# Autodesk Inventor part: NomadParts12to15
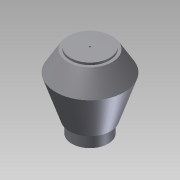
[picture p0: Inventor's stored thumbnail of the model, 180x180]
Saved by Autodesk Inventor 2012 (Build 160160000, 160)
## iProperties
Created: 2012-10
Part Number: NomadParts12to15
Material: Default
Document SubType Name: Modeling
Designer: TechShop Member
Density: 1 g/cm^3
Author: TechShop Member
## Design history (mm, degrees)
sketch "Sketch1"
  geometry: L1 (0, 0)-(57.15, 0); L2 (57.15, 0)-(57.15, 38.1); L3 (57.15, 38.1)-(65.088, 38.1); L4 (107.95, 166.319)-(65.088, 38.1); L5 (0, 236.53)-(61.722, 236.53); L6 (61.722, 236.53)-(61.722, 229.819); L7 (61.722, 229.819)-(70.3, 229.819); L8 (70.3, 229.819)-(107.95, 166.319); L9 (0, 236.53)-(0, 0)
  constraints: 18 end point, 5 perpendicular
  dimensions: "d5" = 57.15 distance of L1.start L1.end; "d6" = 38.1 distance of L1.end L2.end; "d7" = 7.9375 distance of L2.end L3.end; "d9" = 61.722 distance of L5.start L5.end; "d10" = 6.71068 distance of L5.end L6.end; "d11" = 8.57758 distance of L6.end L7.end
revolve "Revolution1" sketch "Sketch1" stored, may be unused: angle "d12" = 90 deg
sketch "Sketch2"
  geometry: C1 r 57.15 at (0, 0) reference; 1 further point
  constraints: 1 coincident
hole "Hole1" sketch "Sketch2" at (0, 0) diameter "d13" = 5.207; stored, may be unused: countersink angle "d17" = 82 deg, drill point angle "d19" = 118 deg; dims "d14" = 19.05, "d15" = 9.525, "d16" = 6.35, "d18" = 25.4
body "Solid1"
